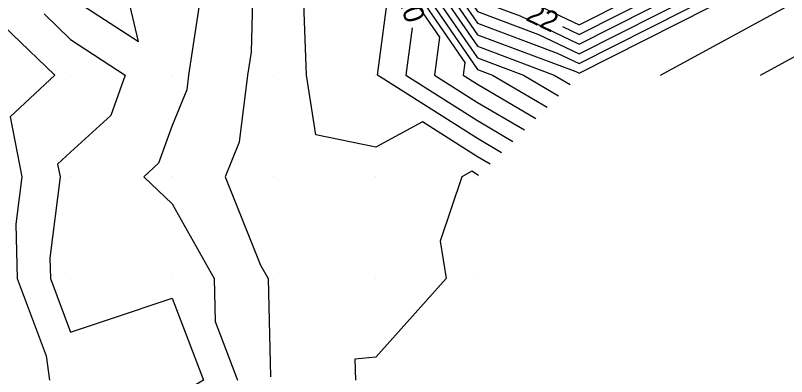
# Model space of a CAD drawing. Extents: x 2531902 to 2533249, y 715219 to 716099.
# Drawn here: x 2532894.6 to 2532970.4, y 715530.4 to 715565.9 of the extents above; entities that cross this region are included whole.
import ezdxf

# ---------------------------------------------------------------- set-up
doc = ezdxf.new("R2010")
doc.units = 0
for name, color, linetype in [('DTM Contours Major', 7, 'Continuous'), ('DTM Contours Major Text', 7, 'Continuous'), ('DTM Contours Minor', 7, 'Continuous'), ('Exist DTM QL2 LIDAR Elevation Point', 7, 'Continuous')]:
    doc.layers.add(name, color=color, linetype=linetype)

msp = doc.modelspace()

# ---------------------------------------------------------------- linework, layer by layer
at = {"layer": 'DTM Contours Major'}
for points in [[(2532957.968, 715560), (2532973.262, 715568.369), (2532972.222, 715570), (2532969.408, 715571.007), (2532969.212, 715570.788), (2532956.037, 715576.037), (2532950, 715578.722), (2532945.552, 715580), (2532940.791, 715582.083), (2532940, 715583.127), (2532932.731, 715590), (2532928.828, 715591.637), (2532921.27, 715592.366), (2532913.266, 715596.734), (2532915.617, 715590), (2532919.56, 715583.804)], [(2532922.727, 715581.475), (2532925.182, 715580), (2532928.631, 715578.631), (2532930, 715578.479), (2532935.093, 715570), (2532940, 715562.836), (2532947.548, 715560), (2532949.093, 715559.093)], [(2532948.344, 715564.785), (2532950, 715563.995), (2532961.812, 715570), (2532953.365, 715573.365)], [(2532897.436, 715566.025), (2532900, 715563.505), (2532905.385, 715560), (2532903.965, 715556.035), (2532900, 715552.425), (2532898.747, 715551.253), (2532898.986, 715550), (2532897.99, 715542.01), (2532898.041, 715540), (2532900, 715534.728), (2532903.958, 715536.042), (2532910, 715538.08), (2532913.078, 715530), (2532910.867, 715528.65), (2532910, 715527.02), (2532901.996, 715528.004), (2532901.486, 715520), (2532901.342, 715518.658), (2532900, 715512.576), (2532899.745, 715510.255), (2532899.452, 715510), (2532896.871, 715506.871), (2532891.779, 715501.154)], [(2532933.591, 715564.662), (2532932.971, 715560), (2532940, 715555.537), (2532943.488, 715553.488)]]:
    msp.add_lwpolyline(points, dxfattribs=at)
at = {"layer": 'DTM Contours Minor'}
for points in [[(2532890.031, 715599.969), (2532900, 715599.902), (2532900.474, 715599.526), (2532910, 715592.582), (2532910.901, 715590), (2532912.479, 715587.521), (2532916.381, 715580), (2532915.862, 715575.862), (2532920, 715577.162), (2532925.128, 715575.128), (2532930, 715574.586), (2532932.755, 715570), (2532938.743, 715561.257), (2532938.576, 715560), (2532940, 715559.096), (2532945.73, 715555.73)], [(2532967.811, 715560), (2532978.405, 715565.797), (2532975.725, 715570), (2532968.473, 715572.594), (2532967.971, 715572.029), (2532956.571, 715576.571), (2532950, 715579.494), (2532948.238, 715580), (2532941.174, 715583.091), (2532940, 715584.639), (2532934.331, 715590), (2532928.142, 715592.595), (2532921.725, 715593.214), (2532910.851, 715599.149), (2532914.045, 715590), (2532920, 715580.643), (2532921.07, 715580), (2532927.464, 715577.464), (2532930, 715577.182), (2532934.313, 715570), (2532940, 715561.698), (2532944.519, 715560), (2532947.972, 715557.972)], [(2532893.5, 715596.5), (2532900, 715596.456), (2532908.146, 715590), (2532910, 715588.289), (2532914.3, 715580), (2532913.483, 715573.483), (2532920, 715575.531), (2532923.96, 715573.96), (2532930, 715573.289), (2532931.975, 715570), (2532936.27, 715563.73), (2532935.774, 715560), (2532940, 715557.317), (2532944.609, 715554.609)], [(2532940.409, 715581.076), (2532940, 715581.615), (2532931.132, 715590), (2532929.514, 715590.678), (2532920.815, 715591.518), (2532915.68, 715594.32), (2532917.188, 715590), (2532920, 715585.582), (2532929.293, 715580), (2532929.799, 715579.799), (2532930, 715579.777), (2532935.872, 715570), (2532940, 715563.973), (2532949.653, 715560.347), (2532950, 715560.182), (2532969.314, 715570), (2532955.502, 715575.502), (2532950, 715577.95), (2532942.867, 715580), (2532940.409, 715581.076)], [(2532900, 715588.776), (2532892.075, 715587.925), (2532895.797, 715580), (2532896.898, 715573.102), (2532897.626, 715570), (2532900, 715567.667), (2532906.683, 715563.317), (2532905.112, 715570), (2532910, 715578.892), (2532910.139, 715580), (2532910, 715580.268), (2532906.535, 715583.465), (2532900, 715588.776)], [(2532940.026, 715580.068), (2532940, 715580.102), (2532938.122, 715581.878), (2532939.245, 715580), (2532931.616, 715578.384), (2532936.651, 715570), (2532940, 715565.111), (2532947.83, 715562.17), (2532950, 715561.135), (2532967.439, 715570), (2532954.968, 715574.968), (2532950, 715577.178), (2532940.181, 715580), (2532940.026, 715580.068)], [(2532954.434, 715574.434), (2532950, 715576.406), (2532941.01, 715578.99), (2532940, 715577.795), (2532933.567, 715576.433), (2532937.431, 715570), (2532940, 715566.249), (2532946.008, 715563.992), (2532950, 715562.088), (2532965.563, 715570), (2532954.434, 715574.434)], [(2532953.9, 715573.9), (2532950, 715575.634), (2532942.093, 715577.907), (2532940, 715575.43), (2532935.519, 715574.481), (2532938.21, 715570), (2532940, 715567.387), (2532944.185, 715565.815), (2532950, 715563.042), (2532963.688, 715570), (2532953.9, 715573.9)], [(2532952.831, 715572.831), (2532950, 715574.09), (2532944.26, 715575.74), (2532940, 715570.701), (2532939.422, 715570.578), (2532939.769, 715570), (2532940, 715569.663), (2532940.54, 715569.46), (2532950, 715564.948), (2532959.937, 715570), (2532952.831, 715572.831)], [(2532942.367, 715552.367), (2532940, 715553.757), (2532930.169, 715560), (2532931.322, 715568.678), (2532930.416, 715570), (2532930, 715570.693), (2532921.625, 715571.625), (2532920, 715572.269), (2532912.781, 715570), (2532912.705, 715567.295), (2532911.614, 715560), (2532911.435, 715558.565), (2532910, 715555.034), (2532908.673, 715551.327), (2532907.214, 715550), (2532910, 715547.35), (2532914.136, 715540), (2532914.239, 715535.761), (2532916.434, 715530)], [(2532941.246, 715551.246), (2532940, 715551.978), (2532934.582, 715555.418), (2532930, 715552.915), (2532924.127, 715554.127), (2532923.216, 715560), (2532922.939, 715567.061), (2532924.565, 715570), (2532920.457, 715570.457), (2532920, 715570.638), (2532917.97, 715570), (2532917.752, 715562.248), (2532917.416, 715560), (2532916.593, 715553.407), (2532915.209, 715550), (2532918.683, 715541.317), (2532919.424, 715540), (2532919.659, 715530.341)], [(2532933.534, 715570), (2532940, 715560.56), (2532941.49, 715560), (2532946.851, 715556.851)], [(2532890, 715568.157), (2532898.484, 715560), (2532894.102, 715555.898), (2532895.225, 715550), (2532894.646, 715545.354), (2532894.783, 715540), (2532897.611, 715532.389), (2532897.955, 715530)], [(2532940.125, 715550.125), (2532940, 715550.198), (2532939.457, 715550.543), (2532938.462, 715550), (2532936.339, 715543.661), (2532936.907, 715540), (2532930, 715532.256), (2532927.945, 715532.055), (2532928.026, 715530)]]:
    msp.add_lwpolyline(points, dxfattribs=at)
at = {"layer": 'Exist DTM QL2 LIDAR Elevation Point'}
for p, q in [((2532900, 715560), (2532900, 715560)), ((2532910, 715560), (2532910, 715560)), ((2532920, 715560), (2532920, 715560)), ((2532930, 715560), (2532930, 715560)), ((2532940, 715560), (2532940, 715560)), ((2532950, 715560), (2532950, 715560)), ((2532900, 715550), (2532900, 715550)), ((2532910, 715550), (2532910, 715550)), ((2532920, 715550), (2532920, 715550)), ((2532930, 715550), (2532930, 715550)), ((2532940, 715550), (2532940, 715550)), ((2532900, 715540), (2532900, 715540)), ((2532910, 715540), (2532910, 715540)), ((2532920, 715540), (2532920, 715540)), ((2532930, 715540), (2532930, 715540)), ((2532940, 715540), (2532940, 715540))]:
    msp.add_line(p, q, dxfattribs=at)

# ---------------------------------------------------------------- texts
at = {"layer": 'DTM Contours Major Text'}
for s, rotation, p in [('20', 288.29004, (2532932.084, 715567.805)), ('22', 334.50323, (2532944.637, 715565.445))]:
    msp.add_text(s, height=2, rotation=rotation, dxfattribs=at).set_placement(p)

doc.saveas('drawing.dxf')
